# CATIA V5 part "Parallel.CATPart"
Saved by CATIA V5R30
Part number: Part1
Bounding box of the stored display mesh (mm): x 0 to 150, y -29.343 to 29.343, z 0 to 29.343
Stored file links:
  D:\PROJECTS\CATIA V56R 2020\Resources\Parts File\c17_catia_v6_6r2020_prt\Parallel.CATPart
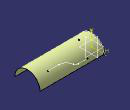
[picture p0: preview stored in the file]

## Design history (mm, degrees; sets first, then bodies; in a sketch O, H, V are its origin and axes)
Set1
  Sketch1 on yz-plane, origin (0, 0, 0), H (0, 1, 0), V (0, 0, 1)
    arc A1 centre (0, 0) radius 29.3431 from (29.3431, 0) to (-29.3431, 0) ccw
  Extrude1: Element1 Sketch1, Lim1 150, Lim2 0
  Sketch2 on zx-plane, origin (0, 0, 0), H (-1, 0, 0), V (0, 0, 1)
    line L1 (-121.5409, 21.8559) -> (-95.9964, 21.8559)
    line L2 (-59.5104, 9.3216) -> (-37.7891, 9.3216)
    arc A1 centre (-95.9964, -22.962) radius 44.8179 from (-95.9964, 21.8559) to (-68.4537, 12.394) cw
    arc A2 centre (-59.5104, 23.8743) radius 14.5527 from (-68.4537, 12.394) to (-59.5104, 9.3216) ccw
    radius A1 = 44.8179
    radius A2 = 14.5527
    horizontal: L1 H, L2 H
    tangency: A1 L1, A2 A1, A2 L2
  Extrude2: Element1 Sketch2, Lim1 150, Lim2 0
  Intersect1: ToIntersect1 Extrude2, ToIntersect2 Extrude1
Body1 (main body)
